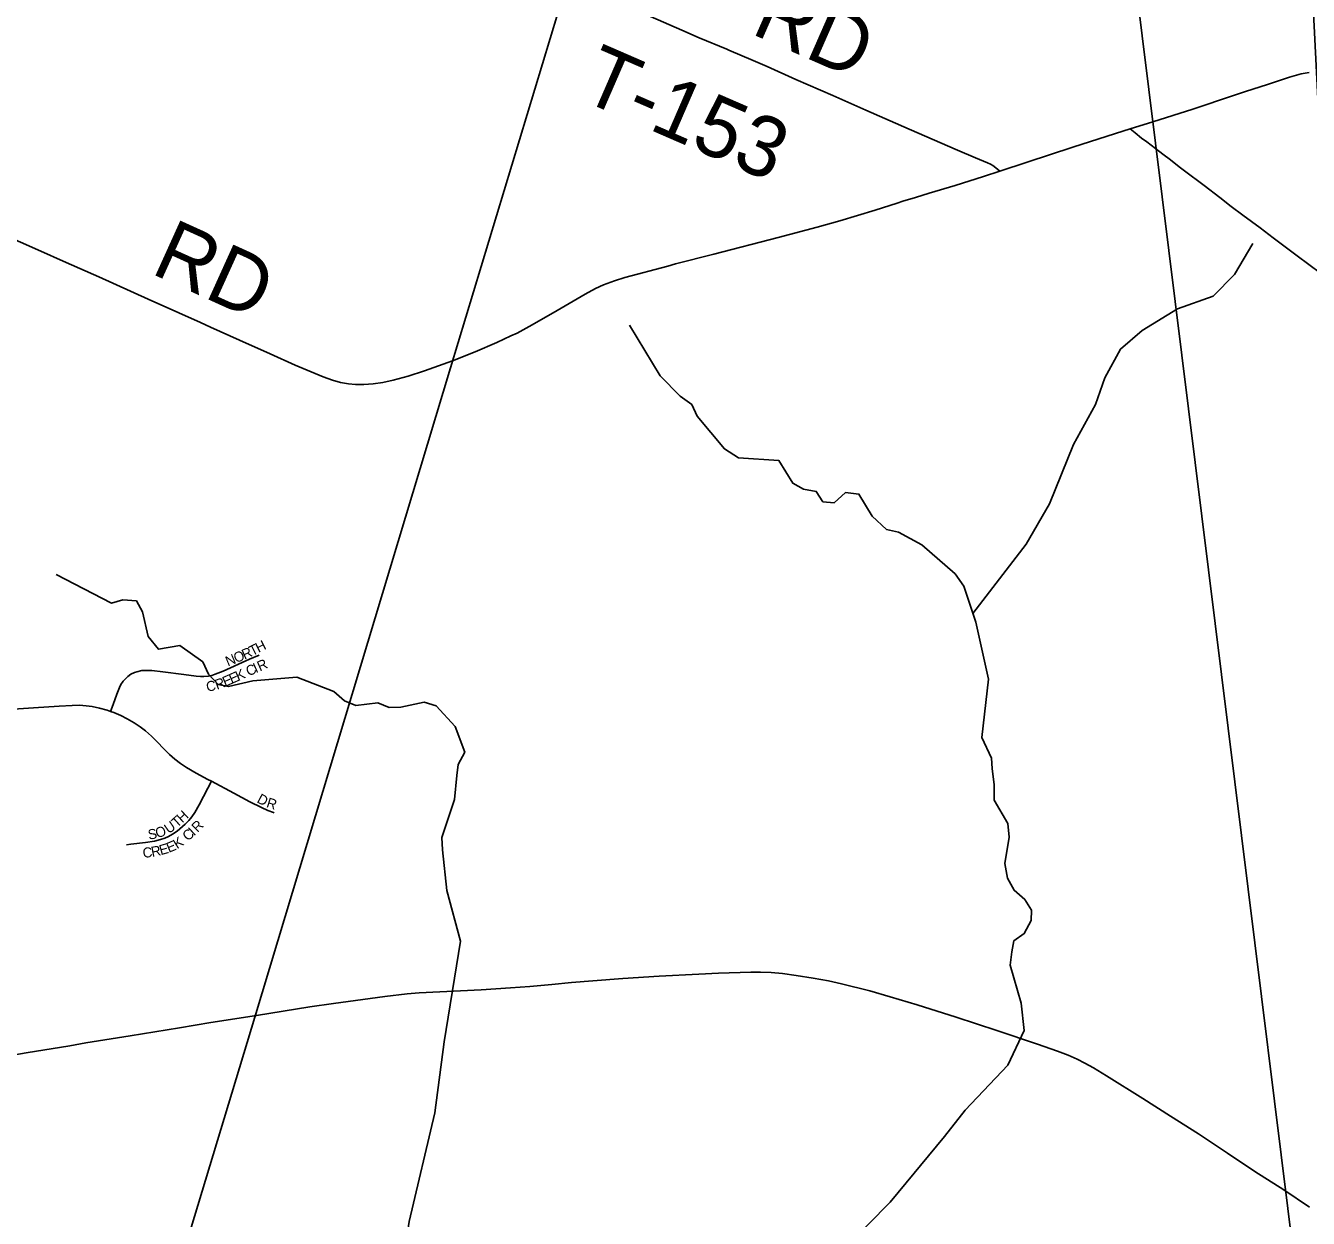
# Model space of a CAD drawing. Extents: x -19.5 to 44.1, y 0 to 22.
# Drawn here: x -17.865 to -16.656, y 16.984 to 18.108 of the extents above; entities that cross this region are included whole.
import ezdxf

# ---------------------------------------------------------------- set-up
doc = ezdxf.new("R2010")
doc.units = 0
for name, color, linetype in [('GM_X_County_Road', 7, 'Continuous'), ('GM_X_County_Road_Text', 7, 'Continuous'), ('GM_X_Minor_River', 7, 'Continuous'), ('GM_X_State_Route', 7, 'Continuous'), ('GM_X_Township', 7, 'Continuous'), ('GM_X_Township_Road', 7, 'Continuous'), ('GM_X_Township_Road_Text', 7, 'Continuous'), ('GM_X_Township_Subdivision', 7, 'Continuous'), ('GM_X_Township_Subdivision_Text', 7, 'Continuous'), ('SH_Text', 7, 'Continuous')]:
    doc.layers.add(name, color=color, linetype=linetype)

msp = doc.modelspace()

# ---------------------------------------------------------------- linework, layer by layer
at = {"layer": 'GM_X_County_Road'}
for points in [[(-16.8237, 18.0111), (-16.8025, 18.0178), (-16.7647, 18.0298), (-16.7263, 18.0425), (-16.7151, 18.0462), (-16.6944, 18.0528), (-16.6735, 18.0597), (-16.6626, 18.0629), (-16.655, 18.0643)], [(-16.9466, 17.9714), (-16.9209, 17.9799), (-16.8777, 17.9938), (-16.8375, 18.0068), (-16.8237, 18.0111)], [(-17.4076, 17.816), (-17.4017, 17.8187), (-17.3902, 17.8248), (-17.3676, 17.8377), (-17.3376, 17.8553), (-17.3277, 17.8607), (-17.3203, 17.864), (-17.3099, 17.8679), (-17.3002, 17.8712), (-17.2595, 17.8819), (-17.2524, 17.8839), (-17.2163, 17.8932), (-17.1555, 17.9088), (-17.1189, 17.9185), (-17.0974, 17.9246), (-17.0641, 17.9345), (-17.0434, 17.9411), (-17.0381, 17.9429), (-17.0262, 17.9464), (-17.0132, 17.9505), (-16.9888, 17.9578), (-16.9622, 17.9663), (-16.9466, 17.9714)], [(-17.946, 17.9381), (-17.8533, 17.8971), (-17.8266, 17.8853), (-17.796, 17.8717), (-17.7495, 17.8508), (-17.7206, 17.8379), (-17.7002, 17.8288), (-17.6906, 17.8244), (-17.6634, 17.8121), (-17.6345, 17.7991), (-17.6107, 17.7886), (-17.5844, 17.7773), (-17.5757, 17.7742), (-17.568, 17.7721), (-17.5607, 17.7709), (-17.554, 17.7703), (-17.546, 17.7702), (-17.5374, 17.7708), (-17.5283, 17.7721), (-17.5186, 17.7742), (-17.5042, 17.7781), (-17.4889, 17.783), (-17.4626, 17.7925), (-17.4413, 17.8009), (-17.4208, 17.8098), (-17.4076, 17.816)]]:
    msp.add_lwpolyline(points, dxfattribs=at)
at = {"layer": 'GM_X_Minor_River'}
for points in [[(-16.972, 17.5545), (-16.9219, 17.6199), (-16.8999, 17.6577), (-16.8772, 17.7138), (-16.8564, 17.7514), (-16.8476, 17.7766), (-16.833, 17.8036), (-16.8126, 17.821), (-16.7792, 17.8416), (-16.7456, 17.8534), (-16.7255, 17.8738), (-16.7082, 17.9031)], [(-16.9519, 17.393), (-16.954, 17.4082), (-16.9545, 17.4181), (-16.9637, 17.4377), (-16.9573, 17.4926), (-16.9692, 17.5461), (-16.9807, 17.5801), (-16.9888, 17.5917), (-17.0201, 17.619), (-17.0423, 17.6312), (-17.0536, 17.6337), (-17.067, 17.6462), (-17.0795, 17.667), (-17.092, 17.6684), (-17.1028, 17.6587), (-17.1134, 17.6597), (-17.1197, 17.6694), (-17.1318, 17.6715), (-17.1419, 17.6771), (-17.1548, 17.6986), (-17.1931, 17.701), (-17.2062, 17.7096), (-17.2318, 17.7405), (-17.2369, 17.7513), (-17.2481, 17.7591), (-17.2667, 17.7785), (-17.2957, 17.8263)], [(-17.4573, 17.412), (-17.451, 17.4236), (-17.46, 17.4478), (-17.4778, 17.4675), (-17.4892, 17.4708), (-17.5112, 17.4663), (-17.5223, 17.4658), (-17.5328, 17.4702), (-17.5537, 17.4677), (-17.5642, 17.4721), (-17.5743, 17.481), (-17.6093, 17.4943), (-17.6507, 17.491), (-17.6736, 17.4855), (-17.6834, 17.4876), (-17.6924, 17.4973), (-17.6978, 17.5088), (-17.7195, 17.5244), (-17.7397, 17.5207), (-17.7493, 17.5327), (-17.7546, 17.556), (-17.7605, 17.5663), (-17.7733, 17.5674), (-17.784, 17.5642), (-17.8362, 17.5912)], [(-17.4583, 17.4016), (-17.4573, 17.412)], [(-17.5198, 16.808), (-17.5082, 16.82), (-17.5155, 16.8555), (-17.5171, 16.8893), (-17.5035, 16.9814), (-17.4792, 17.0838), (-17.4703, 17.1509), (-17.4551, 17.2455), (-17.4679, 17.2933), (-17.472, 17.3318), (-17.4726, 17.3432), (-17.4605, 17.379), (-17.4583, 17.4016)], [(-17.1535, 16.8948), (-17.0501, 16.9998), (-16.9988, 17.0617), (-16.9793, 17.0864), (-16.939, 17.1288), (-16.9236, 17.1616), (-16.9265, 17.1871), (-16.9368, 17.223), (-16.9354, 17.2355), (-16.9333, 17.2461), (-16.9237, 17.2528), (-16.917, 17.2652), (-16.9168, 17.275), (-16.9231, 17.285), (-16.9332, 17.2936), (-16.9394, 17.3051), (-16.9418, 17.3189), (-16.9379, 17.3435), (-16.9391, 17.3564), (-16.952, 17.3784), (-16.9519, 17.393)]]:
    msp.add_lwpolyline(points, dxfattribs=at)
at = {"layer": 'GM_X_State_Route'}
msp.add_lwpolyline([(-17.877, 17.1381), (-17.8643, 17.1403), (-17.8233, 17.1471), (-17.808, 17.1497), (-17.7663, 17.1565), (-17.7199, 17.1639), (-17.7197, 17.164), (-17.6903, 17.1689), (-17.6473, 17.1757), (-17.597, 17.1836), (-17.5748, 17.1868), (-17.5262, 17.1935), (-17.5052, 17.196), (-17.494, 17.1969), (-17.4356, 17.1999), (-17.4078, 17.2016), (-17.3898, 17.2028), (-17.3688, 17.2048), (-17.3503, 17.2067), (-17.3304, 17.2083), (-17.3019, 17.2103), (-17.2678, 17.2125), (-17.2305, 17.2144), (-17.2119, 17.2154), (-17.1815, 17.2165), (-17.1721, 17.2165), (-17.1621, 17.216), (-17.1516, 17.2151), (-17.1386, 17.2134), (-17.1226, 17.2108), (-17.108, 17.2081), (-17.0958, 17.2054), (-17.0693, 17.1987), (-17.0501, 17.1933), (-17.0245, 17.1855), (-16.9878, 17.1739), (-16.9494, 17.1613), (-16.9111, 17.1485), (-16.8923, 17.142), (-16.8824, 17.1382), (-16.8738, 17.1345), (-16.8666, 17.1308), (-16.8584, 17.1263), (-16.8462, 17.1187), (-16.812, 17.0973), (-16.7857, 17.0808), (-16.7595, 17.064), (-16.732, 17.0459), (-16.7062, 17.0287), (-16.679, 17.0112), (-16.6547, 16.9949)], dxfattribs=at)
at = {"layer": 'GM_X_Township'}
msp.add_lwpolyline([(-17.3561, 18.1443), (-17.4643, 17.7858), (-17.649, 17.1741), (-17.7449, 16.8564), (-17.7682, 16.8751), (-17.7757, 16.8847), (-17.8063, 16.9097), (-17.826, 16.9172), (-17.8465, 16.92), (-17.8664, 16.9161), (-17.9065, 16.8978), (-17.926, 16.8931), (-18.0112, 16.8966), (-18.0543, 16.8933), (-18.1184, 16.8749), (-18.1478, 16.8725), (-18.1785, 16.8797), (-18.2096, 16.8937), (-18.2423, 16.9001), (-18.7562, 16.9411), (-18.7834, 16.6305), (-18.8446, 15.9307), (-18.9306, 14.9193), (-19.0014, 14.1)], dxfattribs=at)
at = {"layer": 'GM_X_Township_Road'}
for points in [[(-17.204, 18.0861), (-17.2301, 18.097), (-17.2465, 18.1042), (-17.2759, 18.1171), (-17.2817, 18.1197), (-17.3016, 18.1287), (-17.3189, 18.136), (-17.3426, 18.1461)], [(-16.9466, 17.9714), (-16.9504, 17.9743), (-16.9531, 17.9765), (-16.9554, 17.9778), (-16.9583, 17.979), (-16.9697, 17.9839), (-16.9865, 17.9912), (-17.0322, 18.011), (-17.0731, 18.0289), (-17.1042, 18.0425), (-17.1388, 18.0578), (-17.1661, 18.0698), (-17.1792, 18.0755), (-17.202, 18.0852), (-17.204, 18.0861)], [(-16.6443, 17.8753), (-16.6665, 17.8916), (-16.689, 17.9086), (-16.7014, 17.9178), (-16.7176, 17.9298), (-16.7285, 17.9379), (-16.7392, 17.9463), (-16.7541, 17.9578), (-16.7725, 17.9716), (-16.7775, 17.9755), (-16.7859, 17.982), (-16.7929, 17.9873), (-16.8, 17.9925), (-16.8082, 17.9989), (-16.8132, 18.0025), (-16.8191, 18.0073), (-16.8237, 18.0111)]]:
    msp.add_lwpolyline(points, dxfattribs=at)
at = {"layer": 'GM_X_Township_Subdivision'}
for points in [[(-17.7849, 17.4622), (-17.7825, 17.4688), (-17.779, 17.4785), (-17.7764, 17.4848), (-17.775, 17.4876), (-17.773, 17.4907), (-17.7709, 17.493), (-17.7686, 17.495), (-17.7656, 17.4971), (-17.7623, 17.4987), (-17.76, 17.4996), (-17.7552, 17.5007), (-17.7502, 17.5008), (-17.7459, 17.5006), (-17.7355, 17.4993), (-17.7159, 17.4968), (-17.7042, 17.4953), (-17.7002, 17.495), (-17.6968, 17.4949), (-17.6927, 17.4953), (-17.6895, 17.496), (-17.6862, 17.4971), (-17.6788, 17.5002), (-17.6539, 17.5114), (-17.6448, 17.5153)], [(-17.7849, 17.4622), (-17.7881, 17.4633), (-17.7954, 17.4653), (-17.8021, 17.4667), (-17.8077, 17.4675), (-17.814, 17.4679), (-17.8209, 17.4678), (-17.8333, 17.4672), (-17.8575, 17.4656), (-17.8909, 17.4632)], [(-17.6897, 17.3964), (-17.693, 17.3981), (-17.704, 17.4041), (-17.7131, 17.4094), (-17.7188, 17.4131), (-17.7241, 17.4172), (-17.7292, 17.4216), (-17.7464, 17.4388), (-17.7519, 17.4438), (-17.7569, 17.4477), (-17.7626, 17.4515), (-17.7691, 17.4553), (-17.7753, 17.4584), (-17.7816, 17.4611), (-17.7849, 17.4622)], [(-17.7698, 17.3363), (-17.7657, 17.3369), (-17.752, 17.3386), (-17.7434, 17.34), (-17.7378, 17.3413), (-17.7336, 17.3428), (-17.7301, 17.3443), (-17.7263, 17.3465), (-17.7222, 17.3494), (-17.7145, 17.3558), (-17.7109, 17.3594), (-17.7081, 17.3628), (-17.7053, 17.367), (-17.7012, 17.374), (-17.693, 17.3899), (-17.6897, 17.3964)], [(-17.6307, 17.3667), (-17.6313, 17.3669), (-17.6365, 17.3688), (-17.6427, 17.3715), (-17.6537, 17.377), (-17.6685, 17.385), (-17.6897, 17.3964)]]:
    msp.add_lwpolyline(points, dxfattribs=at)
at = {"layer": 'SH_Text'}
msp.add_lwpolyline([(-16.7391, 19.8563), (-16.538, 15.8887), (-17.0308, 19.8566)], close=True, dxfattribs=at)

# ---------------------------------------------------------------- texts
at = {"layer": 'GM_X_County_Road_Text'}
msp.add_text('RD', height=0.05682, rotation=335.6358, dxfattribs=at).set_placement((-17.7482, 17.8755))
at = {"layer": 'GM_X_Township_Road_Text'}
for s, rotation, p in [('RD', 336.2869, (-17.1825, 18.1014)), ('T-153', 336.5156, (-17.3445, 18.0398))]:
    msp.add_text(s, height=0.05682, rotation=rotation, dxfattribs=at).set_placement(p)
at = {"layer": 'GM_X_Township_Subdivision_Text'}
for s, rotation, p in [('O', 22.685, (-17.6665, 17.5076)), ('R', 24.198, (-17.6586, 17.5109)), ('T', 26.4041, (-17.6514, 17.5142)), ('H', 26.5674, (-17.6454, 17.5172)), ('N', 22.6619, (-17.6742, 17.5044)), ('C', 24.1425, (-17.6547, 17.4951)), ('I', 24.1416, (-17.6479, 17.4981)), ('R', 24.145, (-17.6441, 17.4998)), ('E', 23.4022, (-17.6769, 17.4852)), ('E', 23.992, (-17.6707, 17.4879)), ('K', 24.1255, (-17.6646, 17.4906)), ('C', 8.4083, (-17.694, 17.4808)), ('R', 20.3601, (-17.6845, 17.4824)), ('D', 332.0419, (-17.6476, 17.3768)), ('R', 341.9772, (-17.6386, 17.3722)), ('T', 42.2173, (-17.7222, 17.3521)), ('H', 43.1202, (-17.7172, 17.3566)), ('S', 10.1069, (-17.7487, 17.3412)), ('O', 16.7822, (-17.741, 17.3427)), ('U', 34.7955, (-17.7301, 17.3465)), ('C', 42.0969, (-17.7119, 17.3394)), ('I', 42.4005, (-17.7063, 17.3444)), ('R', 45.3074, (-17.7028, 17.3476)), ('E', 15.6884, (-17.7375, 17.3266)), ('E', 22.4721, (-17.7299, 17.3288)), ('K', 32.7135, (-17.7221, 17.3322)), ('C', 5.765, (-17.7541, 17.3241)), ('R', 10.8, (-17.7457, 17.325))]:
    msp.add_text(s, height=0.00947, rotation=rotation, dxfattribs=at).set_placement(p)

doc.saveas('drawing.dxf')
